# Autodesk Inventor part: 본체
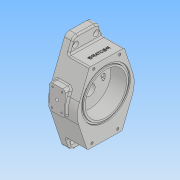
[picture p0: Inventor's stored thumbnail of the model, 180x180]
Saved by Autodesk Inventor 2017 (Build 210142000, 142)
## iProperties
Part Number: 본체
Material: 일반
Document SubType Name: Modeling
Designer: Administrator
Density: 1 g/cm^3
Appearance: 기본값
Author: Administrator
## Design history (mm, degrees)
sketch "스케치1"
  geometry: L1 (-51.832, 18.401)-(-24.317, 94); L2 (-24.317, 94)-(24.317, 94); L3 (24.317, 94)-(51.683, 18.811); L4 (-55, 0)-(55, 0); L5 (-33.78, 68)-(33.78, 68); L6 (-51.832, -18.401)-(-24.317, -94); L7 (-24.317, -94)-(24.317, -94); L8 (24.317, -94)-(51.683, -18.811); L9 (-33.78, -68)-(33.78, -68); A1 r 55 centre (0, 0) between (-51.683, 18.811) and (-55, 0); A2 r 55 centre (0, 0) between (-55, 0) and (-51.683, -18.811); A3 r 55 centre (0, 0) between (51.683, -18.811) and (51.683, 18.811); 3 further points
  constraints: 18 end point, 9 point on circle, 7 symmetric about line, 6 point on line, 5 tangent, 3 centre point, 3 horizontal, 1 coincident, 1 midpoint, 1 vertical alignment
  dimensions: "d2" = 40 deg angle of L3 L1; "d3" = 94 distance from line of point (0, 0) L2; "d4" = 110 distance of L4.start L4.end; "d5" = 68 distance between parallel lines of L4 L5
extrude "돌출1" new body sketch "스케치1" distance "d6" = 55; taper "d7" = 0 deg
extrude "돌출2" join sketch "스케치1" distance "d8" = 15; taper "d9" = 0 deg
sketch "스케치2"
  geometry: L1 (-94, 0)-(-94, 15) reference; L2 (-94, 15)-(-68, 15) reference; L3 (-68, 15)-(-68, 55) reference; L4 (-68, 55)-(68, 55) reference; L5 (68, 55)-(68, 15) reference; L6 (68, 15)-(94, 15) reference; L7 (94, 15)-(94, 0) reference; L8 (94, 0)-(-94, 0) reference; L9 (-94, 0)-(-94, 15) reference; L10 (-94, 15)-(-68, 15) reference; L11 (-68, 15)-(-68, 55) reference; L12 (-68, 55)-(68, 55) reference; L13 (68, 55)-(68, 15) reference; L14 (68, 15)-(94, 15) reference; L15 (94, 15)-(94, 0) reference; L16 (94, 0)-(-94, 0) reference; L17 (18.811, 55)-(-18.811, 55) reference; L18 (9, 0)-(9, 55); L19 (18.811, 55)-(68, 55) reference; L20 (49, 55)-(49, 25); L21 (49, 25)-(9, 25); L22 (49, 55)-(9, 55); 1 further point
  constraints: 8 end point, 4 point on line, 3 perpendicular, 1 collinear
  dimensions: "d10" = 9 distance from line of point (0, 0) L18; "d11" = 30 distance of L20.start L20.end; "d12" = 80 diameter of L20 L18
revolve "회전1" sketch "스케치2" stored, may be unused: angle "d13" = 90 deg
sketch "스케치8"
  geometry: L1 (-51.683, 18.811)-(-24.317, 94) reference; L2 (-24.317, 94)-(24.317, 94) reference; L3 (24.317, 94)-(51.683, 18.811) reference; L4 (51.683, -18.811)-(24.317, -94) reference; L5 (24.317, -94)-(-24.317, -94) reference; L6 (-24.317, -94)-(-51.683, -18.811) reference; C1 r 17.5 at (0, 0); A1 r 55 centre (0, 0) between (-51.683, 18.811) and (-51.683, -18.811) reference; A2 r 55 centre (0, 0) between (51.683, -18.811) and (51.683, 18.811) reference
  constraints: 1 centre point, 1 coincident
  dimensions: "d34" = 35 diameter of C1
extrude "돌출4" join sketch "스케치8" distance "d35" = 5; taper "d36" = 0 deg
sketch "스케치9"
  geometry: L1 (-94, 0)-(-94, 15) reference; L2 (-94, 15)-(-68, 15) reference; L3 (-68, 15)-(-68, 55) reference; L4 (-68, 55)-(-31, 55) reference; L5 (-31, 55)-(-31, 25) reference; L6 (-31, 25)-(49, 25) reference; L7 (49, 25)-(49, 55) reference; L8 (49, 55)-(68, 55) reference; L9 (68, 55)-(68, 15) reference; L10 (68, 15)-(94, 15) reference; L11 (94, 15)-(94, 0) reference; L12 (94, 0)-(17.5, 0) reference; L13 (17.5, 0)-(17.5, -5) reference; L14 (17.5, -5)-(-17.5, -5) reference; L15 (-17.5, -5)-(-17.5, 0) reference; L16 (-17.5, 0)-(-94, 0) reference; L17 (-17.5, -5)-(17.5, -5) reference; L18 (12.5, -5)-(12.5, 3.2); L19 (12.3, 3.4)-(8, 3.4); L20 (8, 3.4)-(8, 15); L21 (8, 15)-(10, 15); L22 (10, 15)-(10, 25); L23 (0, -5)-(0, 25); L24 (12.5, -5)-(0, -5); L25 (10, 25)-(0, 25); A1 r 0.2 centre (12.3, 3.2) between (12.5, 3.2) and (12.3, 3.4); 1 further point
  constraints: 16 end point, 4 perpendicular, 3 point on line, 2 collinear, 2 point on circle, 2 tangent, 2 vertical, 1 centre point, 1 midpoint
  dimensions: "d37" = 8.4 distance between parallel lines of L24 L19; "d38" = 10 distance between parallel lines of L25 L21; "d40" = 25 diameter of L18 L23; "d41" = 20 diameter of L22 L23; "d42" = 16 diameter of L20 L23; "d43" = 0.2 radius of A1 (derived)
revolve "회전3" sketch "스케치9" stored, may be unused: angle "d44" = 90 deg
node "작업 평면2"
sketch "스케치6"
  geometry: L1 (32, 35)-(-14, 35); L2 (-14, 35)-(-14, 5); L3 (-14, 5)-(32, 5); L4 (32, 5)-(32, 35); L5 (32, 35)-(-14, 5); L6 (-14, 35)-(32, 5); L7 (18.811, 0)-(-18.811, 0) reference; 2 further points
  constraints: 12 end point, 2 midpoint, 2 parallel, 1 horizontal, 1 perpendicular
  dimensions: "d26" = 30 distance of L3.end L1.start; "d27" = 46 distance of L2.end L3.end; "d29" = 20 distance from line of L7 point (9, 20); "d30" = 9 horizontal distance of point (0, 0) point (9, 20)
extrude "돌출3" join sketch "스케치6" stored distance "d31" = 4; taper "d32" = 0 deg
sketch "스케치10"
  geometry: L1 (33.78, -68)-(-33.78, -68) reference; L2 (-33.78, -68)-(-51.683, -18.811) reference; L3 (-51.683, 18.811)-(-33.78, 68) reference; L4 (-33.78, 68)-(33.78, 68) reference; L5 (33.78, 68)-(51.683, 18.811) reference; L6 (51.683, -18.811)-(33.78, -68) reference; L7 (33.78, -68)-(-33.78, -68) reference; L8 (-33.78, -68)-(-51.683, -18.811) reference; L9 (-51.683, 18.811)-(-33.78, 68) reference; L10 (-33.78, 68)-(33.78, 68) reference; L11 (33.78, 68)-(51.683, 18.811) reference; L12 (51.683, -18.811)-(33.78, -68) reference; C1 r 40 at (0, 9) reference; C2 r 40 at (0, 9) reference; C3 r 47.5 at (0, 9); C4 r 43.4 at (0, 9); A1 r 55 centre (0, 0) between (-51.683, 18.811) and (-51.683, -18.811) reference; A2 r 55 centre (0, 0) between (51.683, -18.811) and (51.683, 18.811) reference; A3 r 55 centre (0, 0) between (-51.683, 18.811) and (-51.683, -18.811) reference; A4 r 55 centre (0, 0) between (51.683, -18.811) and (51.683, 18.811) reference
  constraints: 2 centre point, 1 coincident
  dimensions: "d45" = 95 diameter of C3; "d46" = 4.1 radial gap between concentric circles of C3 C4
extrude "돌출5" cut sketch "스케치10" distance "d47" = 2.4; taper "d48" = 0 deg
sketch "스케치11"
  geometry: L1 (33.78, -77)-(-33.78, -77) reference; L2 (-33.78, -77)-(-51.683, -27.811) reference; L3 (-53.188, -23)-(-59, -23) reference; L4 (-59, -23)-(-59, 23) reference; L5 (-59, 23)-(-46.883, 23) reference; L6 (-46.883, 23)-(-33.78, 59) reference; L7 (-33.78, 59)-(33.78, 59) reference; L8 (33.78, 59)-(46.883, 23) reference; L9 (46.883, 23)-(59, 23) reference; L10 (59, 23)-(59, -23) reference; L11 (59, -23)-(53.188, -23) reference; L12 (51.683, -27.811)-(33.78, -77) reference; L13 (-26.702, -6)-(-25.515, -6); L14 (25.515, -6)-(26.702, -6); L15 (-26.702, 6)-(-22.517, 6); L16 (22.517, 6)-(26.702, 6); C1 r 40 at (0, 0) reference; C2 r 40 at (0, 0) reference; C3 r 10 at (0, -9) reference; C4 r 10 at (0, -9) reference; A1 r 55 centre (0, -9) between (-53.188, -23) and (-51.683, -27.811) reference; A2 r 55 centre (0, -9) between (51.683, -27.811) and (53.188, -23) reference; A3 r 24 centre (0, -9) between (-20.785, 3) and (-23.552, -4.385); A4 r 24 centre (0, -9) between (23.552, -4.385) and (20.785, 3); A5 r 29 centre (0, 0) between (-28.68, 4.296) and (-28.68, -4.296); A6 r 29 centre (0, 0) between (28.68, -4.296) and (28.68, 4.296); A7 r 2 centre (-22.517, 4) between (-20.785, 3) and (-22.517, 6); A8 r 2 centre (-26.702, 4) between (-26.702, 6) and (-28.68, 4.296); A9 r 2 centre (-26.702, -4) between (-28.68, -4.296) and (-26.702, -6); A10 r 2 centre (-25.515, -4) between (-25.515, -6) and (-23.552, -4.385); A11 r 2 centre (22.517, 4) between (22.517, 6) and (20.785, 3); A12 r 2 centre (26.702, 4) between (28.68, 4.296) and (26.702, 6); A13 r 2 centre (25.515, -4) between (23.552, -4.385) and (25.515, -6); A14 r 2 centre (26.702, -4) between (26.702, -6) and (28.68, -4.296); 8 further points
  constraints: 32 point on circle, 16 tangent, 12 centre point, 8 end point, 8 point on line, 7 equal radius, 4 horizontal, 2 coincident
  dimensions: "d53" = 6 distance from line of C1.centre L15; "d54" = 6 distance from line of C1.centre L16; "d55" = 6 distance from line of C1.centre L14; "d56" = 6 distance from line of L13 C1.centre; "d57" = 29 radius of A5; "d58" = 24 radius of A3; "d59" = 24 radius of A4; "d60" = 29 radius of A6; "d61" = 2 radius of A7
extrude "돌출6" cut sketch "스케치11" distance "d62" = 12; taper "d63" = 0 deg
sketch "스케치12"
  geometry: L1 (0, 0)-(-30, 0) reference; L2 (-30, 0)-(-30, 46) reference; L3 (-30, 46)-(0, 46) reference; L4 (0, 46)-(0, 0) reference; L5 (0, 46)-(0, 0) reference; L6 (0, 23)-(-30, 23); L7 (-30, 32.811)-(-30, 0) reference; L8 (0, 46)-(-30, 46) reference; L9 (-15, 46)-(-15, 0); C1 r 3 at (-15, 23); 1 further point
  constraints: 4 end point, 4 midpoint, 1 centre point, 1 perpendicular, 1 point on line
  dimensions: "d64" = 6 diameter of C1
extrude "돌출7" cut sketch "스케치12" stored distance "d65" = 12; taper "d66" = 0 deg
sketch "스케치13"
  geometry: L1 (0, 0)-(-30, 0) reference; L2 (-30, 0)-(-30, 46) reference; L3 (-30, 46)-(0, 46) reference; L4 (0, 46)-(0, 0) reference; L5 (-24, 6)-(-6, 6); L6 (-6, 6)-(-6, 40); L7 (-6, 40)-(-24, 40); L8 (-24, 40)-(-24, 6); L9 (-24, 6)-(-6, 40); L10 (-6, 6)-(-24, 40); C1 r 3 at (-15, 23) reference; C2 r 3 at (-15, 23) reference; 5 further points
  constraints: 12 end point, 4 coincident, 2 midpoint, 2 parallel, 1 horizontal, 1 perpendicular
  dimensions: "d67" = 18 distance of L6.end L7.end; "d68" = 34 distance of L5.end L6.end
hole "구멍1" sketch "스케치13" at (-24, 40), (-6, 40), (-6, 6), (-24, 6) diameter "d69" = 3.242; stored, may be unused: countersink angle "d73" = 90 deg, drill point angle "d75" = 118 deg; dims "d70" = 8, "d71" = 4, "d72" = 2, "d74" = 10
sketch "스케치14"
  geometry: L1 (-22.517, 15)-(-26.702, 15) reference; L2 (-26.702, 3)-(-25.515, 3) reference; L3 (25.515, 3)-(26.702, 3) reference; L4 (26.702, 15)-(22.517, 15) reference; L5 (33.78, -68)-(-33.78, -68) reference; L6 (-24.317, -94)-(-33.78, -68) reference; L7 (24.317, -94)-(-24.317, -94) reference; L8 (33.78, -68)-(24.317, -94) reference; L9 (51.683, -18.811)-(33.78, -68) reference; L10 (59, -14)-(53.188, -14) reference; L11 (59, 32)-(59, -14) reference; L12 (46.883, 32)-(59, 32) reference; L13 (33.78, 68)-(46.883, 32) reference; L14 (-33.78, 68)-(33.78, 68) reference; L15 (-46.883, 32)-(-33.78, 68) reference; L16 (-59, 32)-(-46.883, 32) reference; L17 (-59, -14)-(-59, 32) reference; L18 (-53.188, -14)-(-59, -14) reference; L19 (-33.78, -68)-(-51.683, -18.811) reference; L20 (24.317, 94)-(33.78, 68) reference; L21 (-24.317, 94)-(24.317, 94) reference; L22 (-33.78, 68)-(-24.317, 94) reference; L23 (-20, -79)-(20, -79); L24 (20, -79)-(20, 79); L25 (20, 79)-(-20, 79); L26 (-20, 79)-(-20, -79); L27 (-20, -79)-(20, 79); L28 (20, -79)-(-20, 79); C1 r 8 at (0, 0) reference; C2 r 10 at (0, 0) reference; C3 r 12.5 at (0, 0) reference; A1 r 2 centre (-26.702, 13) between (-26.702, 15) and (-28.68, 13.296) reference; A2 r 29 centre (0, 9) between (-28.68, 13.296) and (-28.68, 4.704) reference; A3 r 2 centre (-26.702, 5) between (-28.68, 4.704) and (-26.702, 3) reference; A4 r 2 centre (-25.515, 5) between (-25.515, 3) and (-23.552, 4.615) reference; A5 r 24 centre (0, 0) between (-20.785, 12) and (-23.552, 4.615) reference; A6 r 2 centre (-22.517, 13) between (-20.785, 12) and (-22.517, 15) reference; A7 r 24 centre (0, 0) between (23.552, 4.615) and (20.785, 12) reference; A8 r 2 centre (25.515, 5) between (23.552, 4.615) and (25.515, 3) reference; A9 r 2 centre (26.702, 5) between (26.702, 3) and (28.68, 4.704) reference; A10 r 29 centre (0, 9) between (28.68, 4.704) and (28.68, 13.296) reference; A11 r 2 centre (26.702, 13) between (28.68, 13.296) and (26.702, 15) reference; A12 r 2 centre (22.517, 13) between (22.517, 15) and (20.785, 12) reference; A13 r 55 centre (0, 0) between (51.683, -18.811) and (53.188, -14) reference; A14 r 55 centre (0, 0) between (-53.188, -14) and (-51.683, -18.811) reference; 5 further points
  constraints: 12 end point, 4 coincident, 2 midpoint, 2 parallel, 1 horizontal, 1 perpendicular
  dimensions: "d76" = 40 distance of L24.end L25.end; "d77" = 158 distance of L23.end L24.end
hole "구멍2" sketch "스케치14" at (-20, 79), (20, 79), (-20, -79), (20, -79) diameter "d78" = 6.6; stored, may be unused: countersink angle "d82" = 90 deg, drill point angle "d84" = 118 deg; dims "d79" = 8, "d80" = 11, "d81" = 6.6, "d83" = 10
sketch "스케치15"
  geometry: L1 (33.78, -68)-(-33.78, -68) reference; L2 (-33.78, -68)-(-51.683, -18.811) reference; L3 (-51.683, 18.811)-(-33.78, 68) reference; L4 (-33.78, 68)-(33.78, 68) reference; L5 (33.78, 68)-(51.683, 18.811) reference; L6 (51.683, -18.811)-(33.78, -68) reference; L7 (-25, -61)-(25, -61); L8 (25, -61)-(25, 61); L9 (25, 61)-(-25, 61); L10 (-25, 61)-(-25, -61); L11 (-25, -61)-(25, 61); L12 (25, -61)-(-25, 61); C1 r 43.4 at (0, 9) reference; C2 r 47.5 at (0, 9) reference; C3 r 40 at (0, 9) reference; A1 r 55 centre (0, 0) between (-51.683, 18.811) and (-51.683, -18.811) reference; A2 r 55 centre (0, 0) between (51.683, -18.811) and (51.683, 18.811) reference; 4 further points
  constraints: 12 end point, 4 coincident, 2 midpoint, 2 parallel, 1 horizontal, 1 perpendicular
  dimensions: "d85" = 50 distance of L8.end L9.end; "d86" = 122 distance of L7.end L8.end
hole "구멍3" sketch "스케치15" at (-25, 61), (25, 61), (-25, -61), (25, -61) diameter "d87" = 4.917; stored, may be unused: countersink angle "d91" = 90 deg, drill point angle "d93" = 118 deg; dims "d88" = 12, "d89" = 11, "d90" = 6.6, "d92" = 14
sketch "스케치16"
  geometry: L1 (-22.517, 6)-(-26.702, 6) reference; L2 (-26.702, -6)-(-25.515, -6) reference; L3 (25.515, -6)-(26.702, -6) reference; L4 (26.702, 6)-(22.517, 6) reference; L5 (33.78, -77)-(-33.78, -77) reference; L6 (-33.78, -77)-(-51.683, -27.811) reference; L7 (-53.188, -23)-(-59, -23) reference; L8 (-59, -23)-(-59, 23) reference; L9 (-59, 23)-(-46.883, 23) reference; L10 (-46.883, 23)-(-33.78, 59) reference; L11 (-33.78, 59)-(33.78, 59) reference; L12 (33.78, 59)-(46.883, 23) reference; L13 (46.883, 23)-(59, 23) reference; L14 (59, 23)-(59, -23) reference; L15 (59, -23)-(53.188, -23) reference; L16 (51.683, -27.811)-(33.78, -77) reference; C1 r 40 at (0, 0) reference; C2 r 10 at (0, -9) reference; A1 r 24 centre (0, -9) between (-20.785, 3) and (-23.552, -4.385) reference; A2 r 24 centre (0, -9) between (23.552, -4.385) and (20.785, 3) reference; A3 r 2 centre (-26.702, 4) between (-26.702, 6) and (-28.68, 4.296) reference; A4 r 29 centre (0, 0) between (-28.68, 4.296) and (-28.68, -4.296) reference; A5 r 2 centre (-26.702, -4) between (-28.68, -4.296) and (-26.702, -6) reference; A6 r 2 centre (-25.515, -4) between (-25.515, -6) and (-23.552, -4.385) reference; A7 r 24 centre (0, -9) between (-20.785, 3) and (-23.552, -4.385) reference; A8 r 2 centre (-22.517, 4) between (-20.785, 3) and (-22.517, 6) reference; A9 r 24 centre (0, -9) between (23.552, -4.385) and (20.785, 3) reference; A10 r 2 centre (25.515, -4) between (23.552, -4.385) and (25.515, -6) reference; A11 r 2 centre (26.702, -4) between (26.702, -6) and (28.68, -4.296) reference; A12 r 29 centre (0, 0) between (28.68, -4.296) and (28.68, 4.296) reference; A13 r 2 centre (26.702, 4) between (28.68, 4.296) and (26.702, 6) reference; A14 r 2 centre (22.517, 4) between (22.517, 6) and (20.785, 3) reference; A15 r 55 centre (0, -9) between (-53.188, -23) and (-51.683, -27.811) reference; A16 r 55 centre (0, -9) between (51.683, -27.811) and (53.188, -23) reference; 2 further points
  dimensions: "d94" = 26 vertical distance of A2.centre point (-15, 17); "d95" = 26 vertical distance of A1.centre point (15, 17); "d96" = 15 horizontal distance of A1.centre point (15, 17); "d97" = 15 horizontal distance of point (-15, 17) A1.centre
hole "구멍4" sketch "스케치16" at (-15, 17), (15, 17) diameter "d98" = 3.242; stored, may be unused: countersink angle "d102" = 90 deg, drill point angle "d104" = 118 deg; dims "d99" = 8, "d100" = 11, "d101" = 6.6, "d103" = 10
fillet "모깎기1" dims "d105" = 10
fillet "모깎기2" dims "d106" = 5
fillet "모깎기3" dims "d107" = 0.5
fillet "모깎기4" dims "d108" = 3
fillet "모깎기5" dims "d109" = 3
fillet "모깎기7" dims "d111" = 3
chamfer "모따기3" distance "d118" = 0.4; stored, may be unused: second distance "d119" = 2, angle "d120" = 30 deg
chamfer "모따기4" distance "d121" = 1; stored, may be unused: second distance "d122" = 2, angle "d123" = 30 deg
sketch "스케치17"
  geometry: L1 (63.358, 0)-(0, 0) reference; L2 (63.358, 0)-(0, 0) reference; L3 (0, 37)-(0, 0) reference; L4 (0, 37)-(63.358, 37) reference; L5 (63.358, 37)-(63.358, 0) reference; L6 (-2.101, 41.449)-(-2.101, 55) reference; L7 (-2.101, 55)-(65.459, 55) reference; L8 (65.459, 55)-(65.459, 41.449) reference; L9 (-17.947, 28.35)-(81.305, 28.35); L10 (81.305, 28.35)-(81.305, 1.65); L11 (81.305, 1.65)-(-17.947, 1.65); L12 (-17.947, 1.65)-(-17.947, 28.35); L13 (-17.947, 15)-(81.305, 15); L14 (31.679, 28.35)-(31.679, 1.65); 2 further points
  constraints: 5 midpoint, 4 end point, 1 vertical alignment, 4 other
  dimensions: "d124" = 15 distance between parallel lines of L1 L13
feature "엠보싱1" sketch "스케치17" dims "d125" = 0.5, "d126" = 0
fillet "모깎기8" dims "d127" = 2
node "솔리드1"
mirror "미러1"
mirror "미러2"
mirror "미러3"
node "절단 모서리 투영1"
node "절단 모서리 투영2"
node "절단 모서리 투영5"
node "절단 모서리 투영6"
node "절단 모서리 투영7"
node "절단 모서리 투영8"
node "절단 모서리 투영9"
node "절단 모서리 투영10"
node "절단 모서리 투영11"
node "절단 모서리 투영12"
node "절단 모서리 투영13"
node "절단 모서리 투영14"
node "절단 모서리 투영15"
other parameters: "d25" = 59, "d49" = 58, "d50" = 48, "d51" = 6, "d52" = 6
